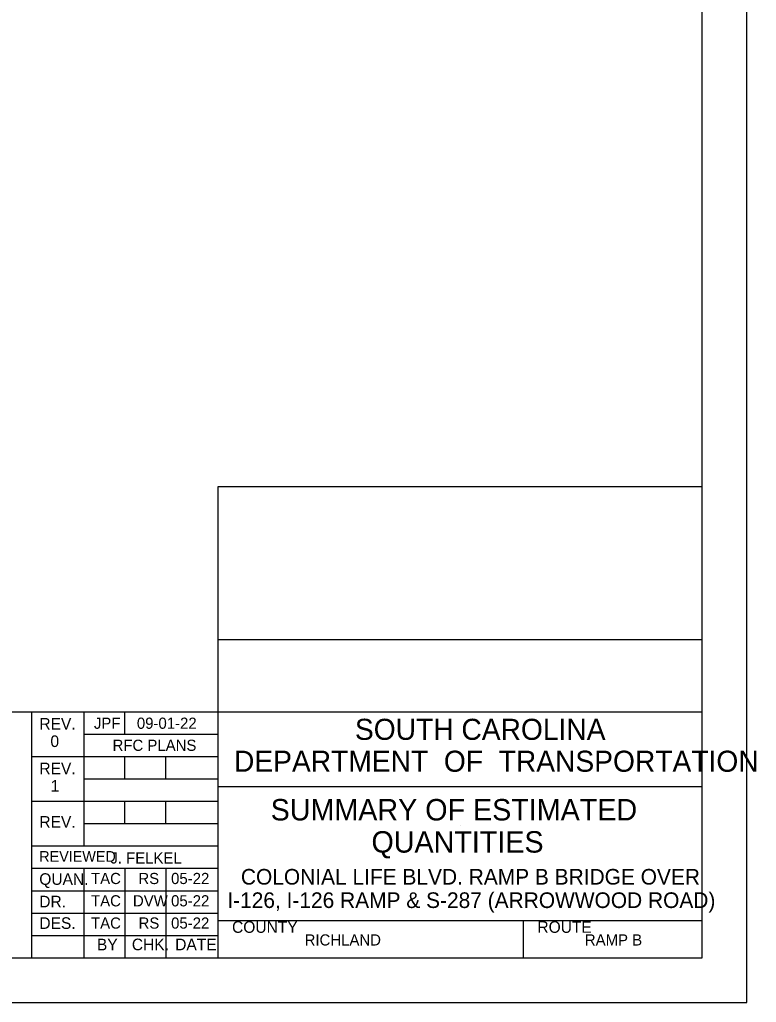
# Model space of a CAD drawing. Extents: x -125.5 to -89.4, y -5.1 to 16.9.
# Drawn here: x -97.67 to -89.43, y -5.07 to 5.93 of the extents above; entities that cross this region are included whole.
import ezdxf

# ---------------------------------------------------------------- set-up
doc = ezdxf.new("R2010")
doc.units = 0
for name, color, linetype in [('BR_BORDER LINES', 7, 'Continuous'), ('BR_TEXT', 7, 'Continuous'), ('Level 31', 7, 'Continuous')]:
    doc.layers.add(name, color=color, linetype=linetype)

msp = doc.modelspace()

# ---------------------------------------------------------------- linework, layer by layer
at = {"layer": 'BR_BORDER LINES'}
for p, q in [((-90.033, -4.566), (-90.033, 16.434)), ((-95.45, -4.566), (-95.45, 0.71)), ((-95.45, 0.71), (-90.033, 0.71)), ((-95.45, -1.004), (-90.033, -1.004)), ((-102.899, -1.816), (-97.534, -1.816)), ((-97.534, -4.566), (-97.534, -1.816)), ((-97.534, -1.816), (-90.033, -1.816)), ((-96.95, -1.816), (-96.95, -3.316)), ((-96.492, -2.066), (-96.492, -1.816)), ((-96.95, -2.066), (-95.45, -2.066)), ((-97.534, -2.316), (-95.45, -2.316)), ((-96.492, -2.566), (-96.492, -2.316)), ((-96.034, -2.566), (-96.034, -2.316)), ((-96.95, -2.566), (-95.45, -2.566)), ((-95.45, -2.649), (-95.45, -2.649)), ((-95.45, -2.649), (-90.033, -2.649)), ((-97.534, -2.816), (-95.45, -2.816)), ((-96.492, -3.066), (-96.492, -2.816)), ((-96.034, -3.066), (-96.034, -2.816)), ((-96.95, -3.066), (-95.45, -3.066)), ((-97.534, -3.316), (-95.45, -3.316)), ((-97.534, -3.566), (-95.45, -3.566)), ((-96.95, -3.566), (-96.95, -4.566)), ((-96.492, -3.566), (-96.492, -4.566)), ((-96.034, -3.566), (-96.034, -4.566)), ((-97.534, -3.816), (-95.45, -3.816)), ((-97.534, -4.066), (-95.45, -4.066)), ((-95.45, -4.149), (-90.033, -4.149)), ((-95.353, -4.149), (-90.033, -4.149)), ((-92.033, -4.566), (-92.033, -4.149)), ((-97.534, -4.316), (-95.45, -4.316)), ((-123.699, -4.566), (-90.033, -4.566))]:
    msp.add_line(p, q, dxfattribs=at)
at = {"layer": 'Level 31'}
msp.add_line((-92.742, -3.09), (-92.742, -3.09), dxfattribs=at)
msp.add_lwpolyline([(-125.533, -5.066), (-89.533, -5.066), (-89.533, 16.934), (-125.533, 16.934)], close=True, dxfattribs=at)

# ---------------------------------------------------------------- texts
at = {"layer": 'BR_TEXT'}
for s, height, p in [('REV.', 0.13, (-97.449, -2.013)), ('JPF', 0.125, (-96.839, -2.004)), ('09-01-22', 0.125, (-96.358, -2.004)), ('SOUTH CAROLINA', 0.23587, (-93.918, -2.128)), ('0', 0.13, (-97.325, -2.208)), ('RFC PLANS', 0.125, (-96.63, -2.251)), ('DEPARTMENT  OF  TRANSPORTATION', 0.23587, (-95.271, -2.485)), ('REV.', 0.13, (-97.449, -2.513)), ('1', 0.13, (-97.323, -2.708)), ('SUMMARY OF ESTIMATED ', 0.24, (-94.861, -3.03)), ('REV.', 0.13, (-97.449, -3.111)), ('QUANTITIES', 0.24, (-93.733, -3.39)), ('REVIEWED', 0.12, (-97.45, -3.493)), ('J. FELKEL', 0.125, (-96.655, -3.512)), ('QUAN.', 0.13, (-97.45, -3.751)), ('TAC', 0.125, (-96.871, -3.742)), ('RS', 0.125, (-96.341, -3.742)), ('05-22', 0.125, (-95.975, -3.742)), ('COLONIAL LIFE BLVD. RAMP B BRIDGE OVER', 0.175, (-95.194, -3.748)), ('I-126, I-126 RAMP & S-287 (ARROWWOOD ROAD) ', 0.175, (-95.346, -4.01)), ('DR.', 0.13, (-97.45, -4.003)), ('TAC', 0.125, (-96.871, -3.992)), ('DVW', 0.125, (-96.402, -3.992)), ('05-22', 0.125, (-95.975, -3.992)), ('DES.', 0.13, (-97.449, -4.244)), ('TAC', 0.125, (-96.871, -4.241)), ('RS', 0.125, (-96.339, -4.241)), ('05-22', 0.125, (-95.975, -4.241)), ('COUNTY', 0.13, (-95.293, -4.288)), ('ROUTE', 0.13, (-91.876, -4.288)), ('BY', 0.13, (-96.805, -4.484)), ('CHK.', 0.13, (-96.414, -4.483)), ('DATE', 0.13, (-95.929, -4.483)), ('RICHLAND', 0.125, (-94.481, -4.43)), ('RAMP B', 0.125, (-91.345, -4.43))]:
    msp.add_text(s, height=height, dxfattribs=at).set_placement(p)

doc.saveas('drawing.dxf')
